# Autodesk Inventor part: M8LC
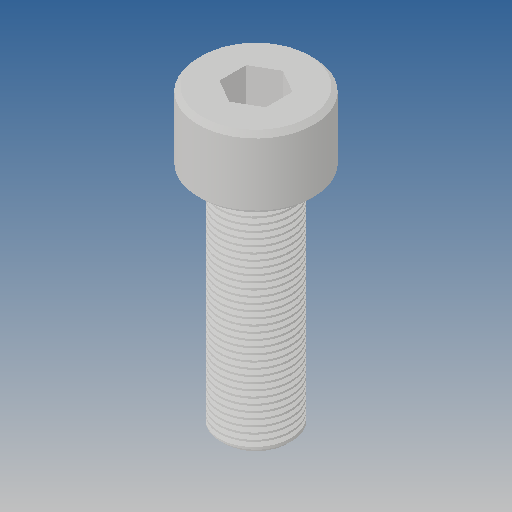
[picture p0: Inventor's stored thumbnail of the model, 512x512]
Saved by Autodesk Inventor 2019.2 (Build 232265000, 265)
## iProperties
Created: 2009-09
Part Number: M8LC
Material: Ogólny
Document SubType Name: Modeling
Designer: CADENGINEERING4
Density: 1 g/cm^3
Appearance: Domyślna
Author: CADENGINEERING4
Revision Number: 1LAST_VERSION
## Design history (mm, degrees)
feature "Baza1"
node "Bryła1"
